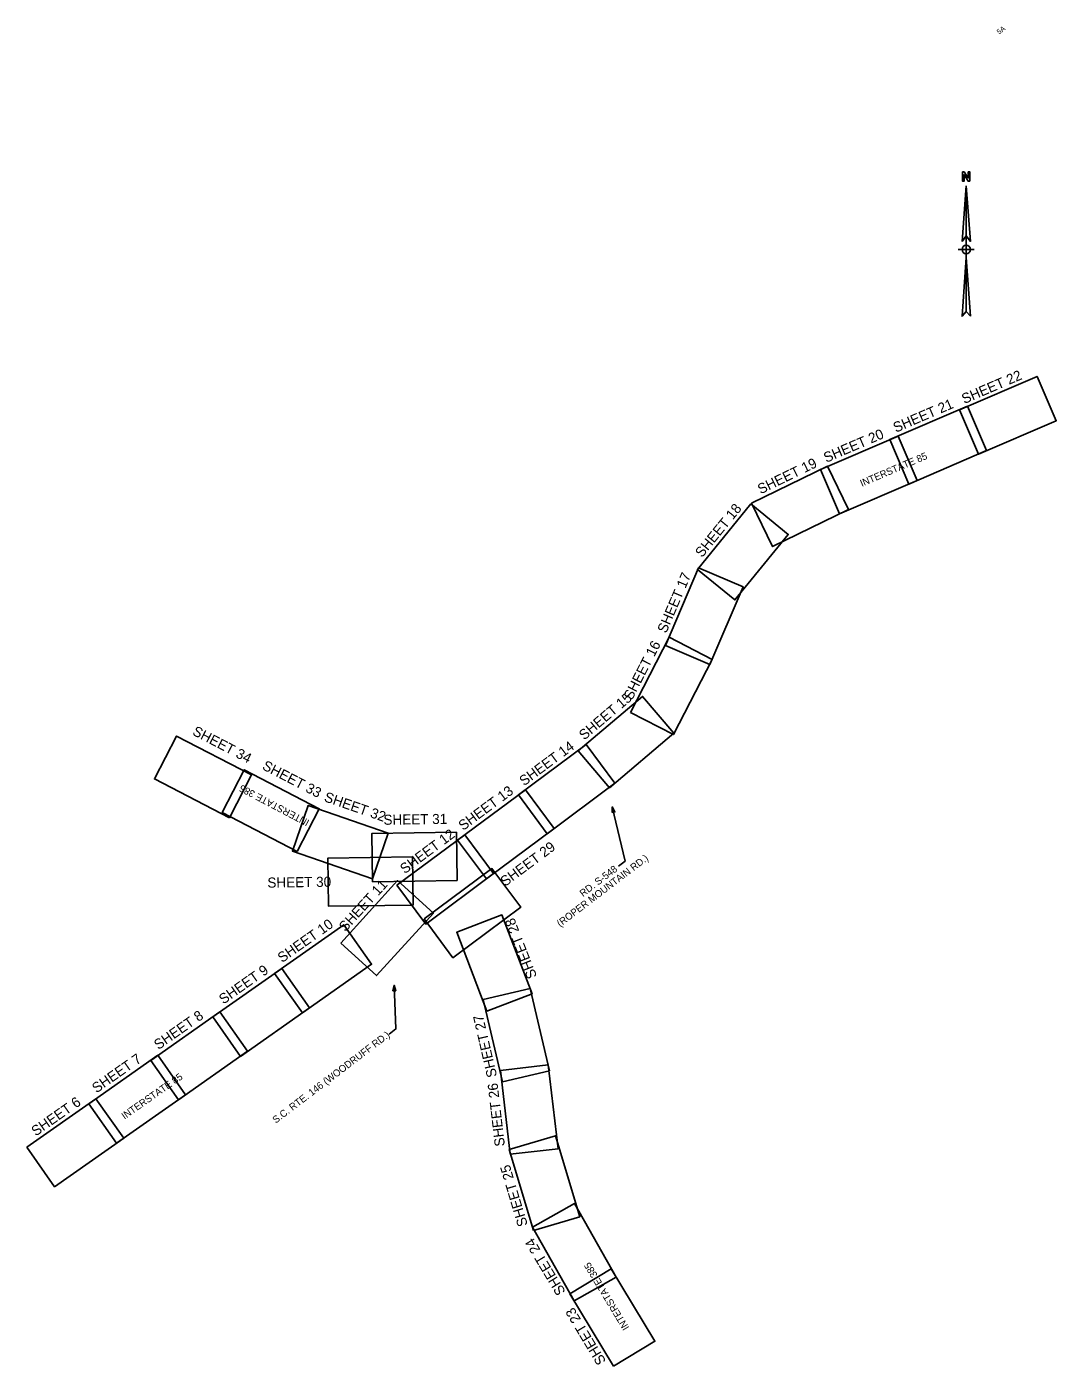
# Model space of a CAD drawing. Extents: x 1602507 to 1642884, y 1084261 to 1112516.
# Drawn here: x 1602507 to 1622906, y 1084261 to 1110806 of the extents above; entities that cross this region are included whole.
import ezdxf

# ---------------------------------------------------------------- set-up
doc = ezdxf.new("R2010")
doc.units = 0
for name, color, linetype in [('RD_EX_OVHD_Poles', 7, 'Continuous'), ('RD_HC_SUR_Bearing_TX400', 7, 'Continuous'), ('RD_HC_temp50_pc_pt', 7, 'Continuous'), ('RD_TX_Misc1', 7, 'Continuous'), ('topo', 7, 'Continuous')]:
    doc.layers.add(name, color=color, linetype=linetype)

msp = doc.modelspace()

# ---------------------------------------------------------------- linework, layer by layer
at = {"layer": 'RD_EX_OVHD_Poles'}
for p, q in [((1621123, 1107653), (1621040, 1106552)), ((1621123, 1106665), (1621040, 1106552)), ((1621123, 1106665), (1621123, 1106232)), ((1621282, 1106393), (1620966, 1106393)), ((1621123, 1106232), (1621206, 1105069)), ((1621206, 1105069), (1621123, 1105162))]:
    msp.add_line(p, q, dxfattribs=at)
msp.add_lwpolyline([(1621195, 1107746), (1621165, 1107746), (1621082, 1107879), (1621082, 1107859), (1621082, 1107746), (1621052, 1107746), (1621052, 1107931), (1621082, 1107931), (1621165, 1107808), (1621165, 1107818), (1621165, 1107931), (1621195, 1107931), (1621195, 1107746)], dxfattribs=at)
for points in [[(1621123, 1107653), (1621206, 1106552), (1621123, 1106665)], [(1621123, 1106232), (1621123, 1105162), (1621040, 1105069)]]:
    msp.add_lwpolyline(points, close=True, dxfattribs=at)
msp.add_circle((1621124, 1106393), 83.8, dxfattribs=at)
at = {"layer": 'RD_HC_temp50_pc_pt'}
for points in [[(1614108, 1095233), (1614162, 1095246), (1614109, 1095347)], [(1609763, 1091702), (1609818, 1091704), (1609786, 1091813)]]:
    msp.add_lwpolyline(points, close=True, dxfattribs=at)
for points in [[(1614109, 1095347), (1614365, 1094271), (1614233, 1094171)], [(1609786, 1091813), (1609820, 1090946), (1609688, 1090845)]]:
    msp.add_lwpolyline(points, dxfattribs=at)
at = {"layer": 'topo'}
for points in [[(1620990, 1103216), (1622529, 1103876), (1622906, 1102998), (1621367, 1102337)], [(1619612, 1102624), (1621151, 1103285), (1621528, 1102406), (1619989, 1101745)], [(1618233, 1102033), (1619772, 1102693), (1620150, 1101814), (1618610, 1101154)], [(1616869, 1101365), (1618375, 1102097), (1618793, 1101237), (1617287, 1100504)], [(1615797, 1100052), (1616855, 1101351), (1617597, 1100747), (1616539, 1099448)], [(1615161, 1098546), (1615821, 1100085), (1616700, 1099708), (1616040, 1098169)], [(1614471, 1097216), (1615234, 1098707), (1616086, 1098270), (1615322, 1096780)], [(1613433, 1096454), (1614711, 1097536), (1615329, 1096806), (1614051, 1095724)], [(1606522, 1095130), (1605035, 1095900), (1605475, 1096749), (1606962, 1095979)], [(1612249, 1095583), (1613593, 1096582), (1614163, 1095814), (1612819, 1094815)], [(1607863, 1094461), (1606376, 1095232), (1606816, 1096081), (1608303, 1095311)], [(1611045, 1094688), (1612389, 1095687), (1612960, 1094919), (1611615, 1093920)], [(1609355, 1093923), (1607772, 1094471), (1608085, 1095375), (1609668, 1094827)], [(1611035, 1093888), (1609360, 1093863), (1609346, 1094820), (1611021, 1094845)], [(1609841, 1093793), (1611185, 1094792), (1611756, 1094025), (1610412, 1093025)], [(1610162, 1093400), (1608488, 1093376), (1608473, 1094332), (1610148, 1094357)], [(1610380, 1093126), (1611724, 1094125), (1612295, 1093358), (1610950, 1092358)], [(1608729, 1092645), (1609856, 1093885), (1610564, 1093241), (1609437, 1092002)], [(1611626, 1091298), (1611028, 1092863), (1611922, 1093204), (1612520, 1091639)], [(1607418, 1092045), (1608787, 1093010), (1609338, 1092228), (1607969, 1091263)], [(1606191, 1091184), (1607562, 1092146), (1608111, 1091363), (1606740, 1090401)], [(1611931, 1089900), (1611553, 1091532), (1612485, 1091748), (1612863, 1090116)], [(1604963, 1090323), (1606334, 1091285), (1606883, 1090502), (1605512, 1089540)], [(1603735, 1089462), (1605106, 1090423), (1605655, 1089640), (1604284, 1088679)], [(1603735, 1089462), (1605106, 1090423), (1605655, 1089640), (1604284, 1088679)], [(1612085, 1088461), (1611891, 1090125), (1612841, 1090236), (1613035, 1088572)], [(1602507, 1088600), (1603878, 1089562), (1604427, 1088779), (1603056, 1087817)], [(1612550, 1086950), (1612068, 1088554), (1612984, 1088829), (1613466, 1087225)], [(1613351, 1085556), (1612526, 1087014), (1613358, 1087485), (1614183, 1086027)], [(1614134, 1084261), (1613269, 1085696), (1614089, 1086190), (1614953, 1084755)]]:
    msp.add_lwpolyline(points, close=True, dxfattribs=at)

# ---------------------------------------------------------------- texts
at = {"layer": 'RD_HC_SUR_Bearing_TX400'}
for s, rotation, p in [('SHEET 22', 23.2284, (1621085, 1103329)), ('SHEET 21', 23.2284, (1619728, 1102760)), ('SHEET 20', 23.2284, (1618349, 1102164)), ('SHEET 19', 25.9305, (1617049, 1101539)), ('SHEET 18', 50.8545, (1615888, 1100275)), ('SHEET 17', 66.7846, (1615177, 1098775)), ('SHEET 16', 62.865, (1614499, 1097448)), ('SHEET 15', 40.265, (1613553, 1096660)), ('SHEET 34', 332.6325, (1605773, 1096783)), ('SHEET 14', 36.6256, (1612361, 1095753)), ('SHEET 33', 332.6268, (1607157, 1096100)), ('SHEET 32', 340.9029, (1608385, 1095461)), ('SHEET 13', 36.6256, (1611154, 1094868)), ('SHEET 31', 0.8477, (1609576, 1094991)), ('SHEET 12', 36.6256, (1609996, 1094010)), ('SHEET 29', 36.6256, (1611986, 1093760)), ('SHEET 30', 0.8477, (1607276, 1093745)), ('SHEET 11', 47.7138, (1608820, 1092860)), ('SHEET 10', 35.1662, (1607566, 1092250)), ('SHEET 28', 111.3687, (1612621, 1091986)), ('SHEET 9', 35.0468, (1606403, 1091427)), ('SHEET 8', 35.0468, (1605115, 1090525)), ('SHEET 27', 103.0488, (1611828, 1090009)), ('SHEET 7', 35.0468, (1603887, 1089666)), ('SHEET 7', 35.0468, (1603887, 1089666)), ('SHEET 26', 96.6561, (1611982, 1088628)), ('SHEET 6', 35.0468, (1602685, 1088812)), ('SHEET 25', 106.7335, (1612437, 1087062)), ('SHEET 24', 121.0768, (1613191, 1085740)), ('SHEET 23', 121.0768, (1613993, 1084361))]:
    msp.add_text(s, height=200, rotation=rotation, dxfattribs=at).set_placement(p)
at = {"layer": 'RD_HC_temp50_pc_pt'}
for s, rotation, p in [('INTERSTATE 85', 23.2284, (1619056, 1101688)), ('INTERSTATE 385', 152.2132, (1608119, 1095080)), ('(ROPER MOUNTAIN RD.)', 37.3059, (1613076, 1092961)), ('RD. S-548', 37.3059, (1613529, 1093557)), ('S.C. RTE. 146 (WOODRUFF RD.)', 37.3059, (1607441, 1089067)), ('INTERSTATE 85', 35.0468, (1604444, 1089147)), ('INTERSTATE 385', 121.0768, (1614450, 1085026))]:
    msp.add_text(s, height=140, rotation=rotation, dxfattribs=at).set_placement(p)
at = {"layer": 'RD_TX_Misc1'}
msp.add_text('5A', height=100, rotation=37.3059, dxfattribs=at).set_placement((1621775, 1110650))

doc.saveas('drawing.dxf')
